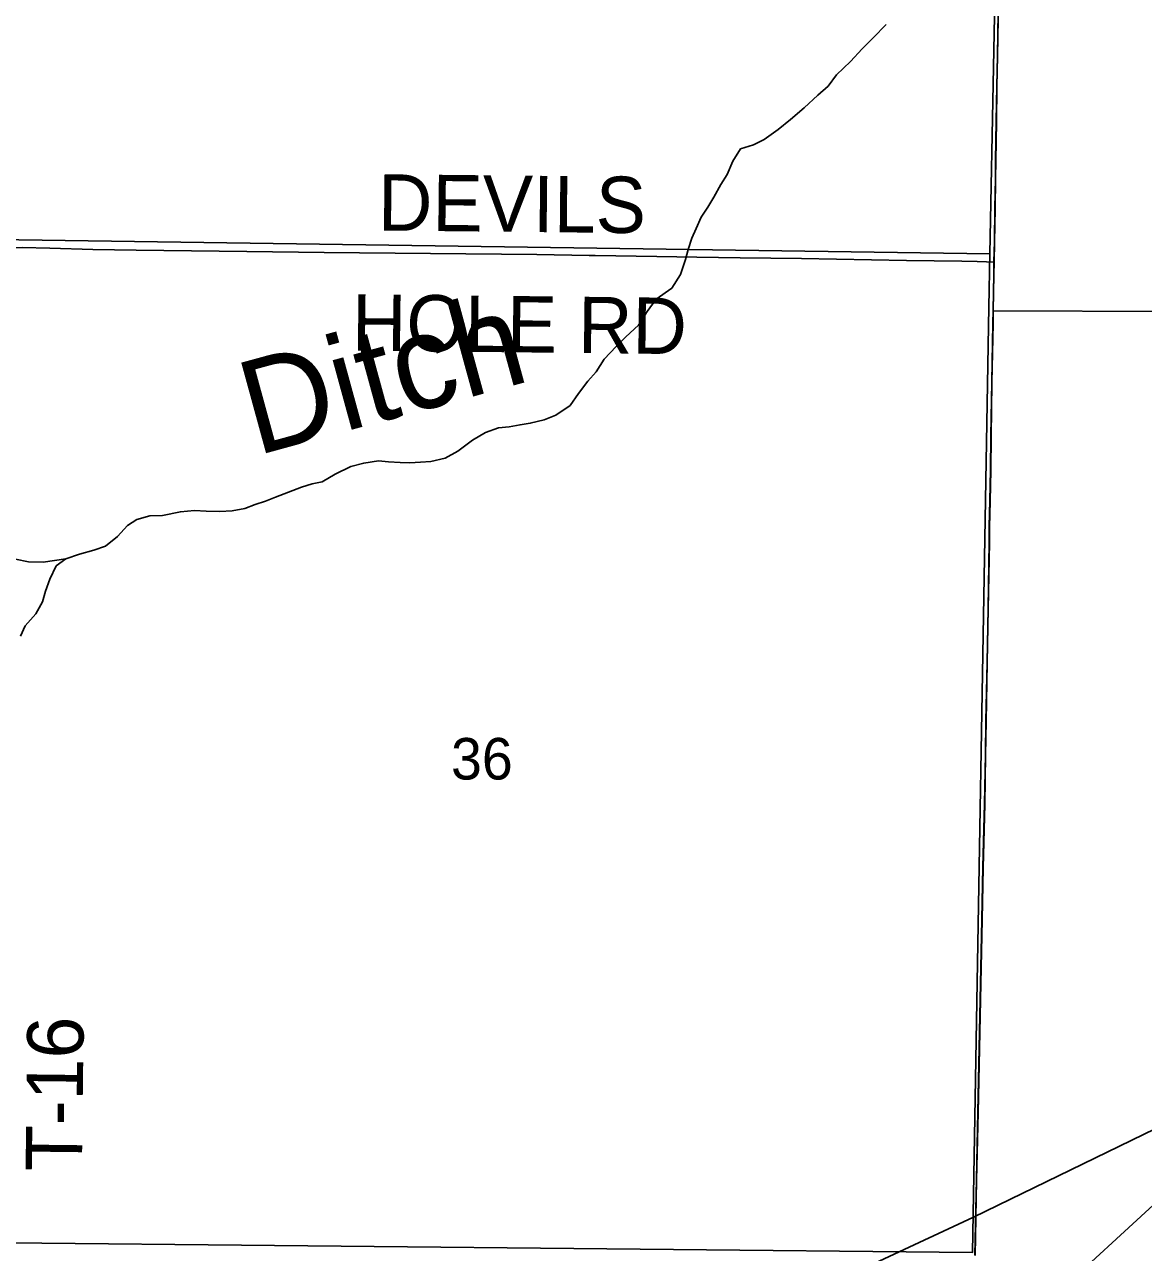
# Model space of a CAD drawing. Extents: x 0 to 34, y 0 to 22.
# Drawn here: x 6.172 to 7.301, y 18.499 to 19.739 of the extents above; entities that cross this region are included whole.
import ezdxf

# ---------------------------------------------------------------- set-up
doc = ezdxf.new("R2010")
doc.units = 0
for name, color, linetype in [('Default', 7, 'Continuous'), ('GM_X_Minor_River', 7, 'Continuous'), ('GM_X_Minor_River_Text', 7, 'Continuous'), ('GM_X_Rail_Line', 7, 'Continuous'), ('GM_X_Section', 7, 'Continuous'), ('GM_X_Section_Text', 7, 'Continuous'), ('GM_X_State_Route', 7, 'Continuous'), ('GM_X_Township_Road', 7, 'Continuous'), ('GM_X_Township_Road_Text', 7, 'Continuous'), ('GM_X_US_Route', 7, 'Continuous'), ('SH_Cut_Line', 7, 'Continuous')]:
    doc.layers.add(name, color=color, linetype=linetype)

msp = doc.modelspace()

# ---------------------------------------------------------------- linework, layer by layer
at = {"layer": 'Default'}
for points in [[(7.1309, 18.4967), (7.1325, 18.5729), (7.134, 18.6413), (7.135, 18.6895), (7.1364, 18.7547), (7.1381, 18.8355), (7.139, 18.8884), (7.1408, 18.9521), (7.1415, 19.0018), (7.1421, 19.036), (7.1432, 19.0951), (7.1442, 19.1495), (7.1454, 19.2163), (7.1455, 19.2319), (7.1459, 19.2583), (7.1468, 19.2893), (7.1472, 19.3236), (7.148, 19.3779), (7.1491, 19.437), (7.1493, 19.4501), (7.1499, 19.4867), (7.1502, 19.4995), (7.1507, 19.5194), (7.1511, 19.5536), (7.1517, 19.5831), (7.1519, 19.6018), (7.1525, 19.6406), (7.153, 19.6764), (7.1537, 19.7074), (7.1558, 19.838)], [(7.1558, 19.838), (7.1537, 19.7074), (7.153, 19.6764), (7.1525, 19.6406), (7.1519, 19.6018), (7.1517, 19.5831), (7.1511, 19.5536), (7.1507, 19.5194), (7.1502, 19.4995), (7.1499, 19.4867), (7.1493, 19.4501), (7.1491, 19.437), (7.148, 19.3779), (7.1472, 19.3236), (7.1468, 19.2893), (7.1459, 19.2583), (7.1455, 19.2319), (7.1454, 19.2163), (7.1442, 19.1495), (7.1432, 19.0951), (7.1421, 19.036), (7.1415, 19.0018), (7.1408, 18.9521), (7.139, 18.8884), (7.1381, 18.8355), (7.1364, 18.7547), (7.135, 18.6895), (7.134, 18.6413), (7.1325, 18.5729), (7.1309, 18.4967)]]:
    msp.add_lwpolyline(points, dxfattribs=at)
at = {"layer": 'GM_X_Minor_River'}
for points in [[(7.0416, 19.7385), (7.0284, 19.7252), (7.0172, 19.7141), (7.0055, 19.7014), (6.9915, 19.6877), (6.9829, 19.6762), (6.9724, 19.6673), (6.9589, 19.6544), (6.9449, 19.6426), (6.9326, 19.6326), (6.9183, 19.6224), (6.9076, 19.6173), (6.8946, 19.6131), (6.8867, 19.6007), (6.8811, 19.5872), (6.8748, 19.5771), (6.8676, 19.5644), (6.8617, 19.5543), (6.855, 19.5442), (6.8498, 19.5326), (6.8454, 19.5228), (6.8417, 19.5115), (6.8392, 19.5013), (6.8339, 19.4863), (6.8252, 19.4724), (6.8094, 19.4614), (6.8004, 19.4491), (6.7917, 19.4353), (6.7789, 19.4235), (6.7692, 19.4135), (6.7572, 19.4008), (6.7489, 19.3881), (6.7407, 19.3785), (6.7313, 19.3662), (6.7227, 19.3542), (6.7084, 19.3443), (6.6966, 19.3397), (6.6825, 19.3362), (6.6722, 19.3346), (6.6612, 19.3326), (6.6505, 19.3317), (6.6375, 19.3267), (6.6241, 19.3191), (6.6094, 19.308), (6.5968, 19.3011), (6.5823, 19.2977), (6.5717, 19.2968), (6.5611, 19.2963), (6.5512, 19.2965), (6.5395, 19.2972), (6.5293, 19.2982), (6.5145, 19.2959), (6.5015, 19.2924), (6.4858, 19.2849), (6.4727, 19.2772), (6.4624, 19.2752), (6.4518, 19.2716), (6.4388, 19.2666), (6.4254, 19.2616), (6.4154, 19.2577), (6.4051, 19.2542), (6.3948, 19.2502), (6.3819, 19.2479), (6.3693, 19.2471), (6.3557, 19.2474), (6.344, 19.2481), (6.3296, 19.2469), (6.3117, 19.2432), (6.2988, 19.2427), (6.2858, 19.2392), (6.2762, 19.233), (6.2661, 19.2219), (6.2541, 19.2123), (6.2423, 19.208), (6.2278, 19.2042), (6.214, 19.1992), (6.2044, 19.1922), (6.198, 19.1787), (6.1935, 19.1667), (6.1906, 19.1558)], [(6.214, 19.1992), (6.1912, 19.196), (6.1765, 19.1963), (6.1633, 19.1989)], [(6.1906, 19.1558), (6.1839, 19.1438), (6.173, 19.1319), (6.1685, 19.1214)]]:
    msp.add_lwpolyline(points, dxfattribs=at)
at = {"layer": 'GM_X_Rail_Line'}
for points in [[(7.1295, 18.535), (7.5214, 18.7256), (7.5415, 18.727), (7.7361, 18.8905), (7.8156, 18.9525), (8.1721, 19.3059), (8.3177, 19.4462), (8.6699, 19.8071), (8.8197, 19.9527), (8.8503, 19.9748), (8.9, 19.9949)], [(5.1236, 17.5022), (5.2885, 17.5882), (5.4372, 17.6568), (5.858, 17.9153), (6.1629, 18.1611), (6.3042, 18.1643), (6.4687, 18.2265), (7.1295, 18.535)]]:
    msp.add_lwpolyline(points, dxfattribs=at)
at = {"layer": 'GM_X_Section'}
for points in [[(7.1654, 20.5062), (7.1646, 20.4494), (7.146, 19.507), (6.1433, 19.5215), (6.1602, 20.5302)], [(7.146, 19.507), (7.145, 19.4532), (7.1287, 18.4994), (6.1226, 18.5095), (6.1433, 19.5215)]]:
    msp.add_lwpolyline(points, close=True, dxfattribs=at)
at = {"layer": 'GM_X_State_Route'}
msp.add_lwpolyline([(7.1275, 18.3685), (7.1654, 18.4136), (7.3608, 18.5932), (7.4758, 18.6969), (7.6618, 18.8326), (7.7258, 18.8796), (7.8269, 18.9622), (7.9458, 19.0794), (8.0941, 19.2274), (8.2454, 19.3754), (8.3174, 19.4447), (8.6611, 19.7985), (8.7135, 19.8476), (8.8036, 19.9332), (8.8247, 19.9539), (8.842, 19.9695), (8.8812, 19.988), (8.9, 19.9963)], dxfattribs=at)
at = {"layer": 'GM_X_Township_Road'}
msp.add_line((7.1495, 19.4496), (8.3174, 19.4447), dxfattribs=at)
msp.add_lwpolyline([(6.1472, 19.5128), (6.1512, 19.5131), (6.1574, 19.5133), (6.1699, 19.5134), (6.1979, 19.5128), (6.2414, 19.5116), (6.2849, 19.5109), (6.3408, 19.5102), (6.3968, 19.5096), (6.4745, 19.5085), (6.689, 19.5064), (6.7418, 19.5056), (6.748, 19.5055), (6.8102, 19.5044), (6.8506, 19.5037), (6.8941, 19.5032), (6.9562, 19.5023), (7.0619, 19.5005), (7.1178, 19.4997), (7.1334, 19.4995), (7.1427, 19.4992), (7.1504, 19.4989)], dxfattribs=at)
at = {"layer": 'GM_X_US_Route'}
msp.add_lwpolyline([(7.1312, 18.4962), (7.1327, 18.5723), (7.1343, 18.6407), (7.1352, 18.6889), (7.1366, 18.7542), (7.1383, 18.835), (7.1393, 18.8878), (7.141, 18.9515), (7.1417, 19.0013), (7.1424, 19.0355), (7.1434, 19.0945), (7.1444, 19.1489), (7.1456, 19.2158), (7.1457, 19.2313), (7.1462, 19.2577), (7.147, 19.2888), (7.1474, 19.323), (7.1482, 19.3774), (7.1493, 19.4365), (7.1495, 19.4496), (7.1501, 19.4862), (7.1504, 19.4989), (7.1509, 19.5188), (7.1514, 19.553), (7.1519, 19.5825), (7.1521, 19.6012), (7.1528, 19.64), (7.1532, 19.6758), (7.1539, 19.7069), (7.156, 19.8374)], dxfattribs=at)
at = {"layer": 'SH_Cut_Line'}
for points in [[(7.1309, 18.4967), (7.1325, 18.5729), (7.134, 18.6413), (7.135, 18.6895), (7.1364, 18.7547), (7.1381, 18.8355), (7.139, 18.8884), (7.1408, 18.9521), (7.1415, 19.0018), (7.1421, 19.036), (7.1432, 19.0951), (7.1442, 19.1495), (7.1454, 19.2163), (7.1455, 19.2319), (7.1459, 19.2583), (7.1468, 19.2893), (7.1472, 19.3236), (7.148, 19.3779), (7.1491, 19.437), (7.1493, 19.4501), (7.1499, 19.4867), (7.1502, 19.4995), (7.1507, 19.5194), (7.1511, 19.5536), (7.1517, 19.5831), (7.1519, 19.6018), (7.1525, 19.6406), (7.153, 19.6764), (7.1537, 19.7074), (7.1558, 19.838)], [(7.1558, 19.838), (7.1537, 19.7074), (7.153, 19.6764), (7.1525, 19.6406), (7.1519, 19.6018), (7.1517, 19.5831), (7.1511, 19.5536), (7.1507, 19.5194), (7.1502, 19.4995), (7.1499, 19.4867), (7.1493, 19.4501), (7.1491, 19.437), (7.148, 19.3779), (7.1472, 19.3236), (7.1468, 19.2893), (7.1459, 19.2583), (7.1455, 19.2319), (7.1454, 19.2163), (7.1442, 19.1495), (7.1432, 19.0951), (7.1421, 19.036), (7.1415, 19.0018), (7.1408, 18.9521), (7.139, 18.8884), (7.1381, 18.8355), (7.1364, 18.7547), (7.135, 18.6895), (7.134, 18.6413), (7.1325, 18.5729), (7.1309, 18.4967)]]:
    msp.add_lwpolyline(points, dxfattribs=at)

# ---------------------------------------------------------------- texts
at = {"layer": 'GM_X_Minor_River_Text'}
msp.add_text('Ditch', height=0.09475, rotation=15.3113, dxfattribs=at).set_placement((6.406, 19.3032))
at = {"layer": 'GM_X_Section_Text'}
msp.add_text('36', height=0.04186, rotation=0, dxfattribs=at).set_placement((6.6026, 18.9767))
at = {"layer": 'GM_X_Township_Road_Text'}
for s, rotation, p in [('DEVILS', 359.4218, (6.5287, 19.5307)), ('HOLE RD', 359.3614, (6.5024, 19.4096)), ('T-16', 89.3118, (6.2303, 18.5809))]:
    msp.add_text(s, height=0.05682, rotation=rotation, dxfattribs=at).set_placement(p)

doc.saveas('drawing.dxf')
